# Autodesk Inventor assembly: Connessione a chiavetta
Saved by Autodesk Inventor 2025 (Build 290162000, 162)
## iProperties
Created: 2026-05
Part Number: Connessione a chiavetta
Document SubType Name: Assembly
Designer: Ryzen5700u
ClientObjectVersion: 1
Author: Ryzen5700u
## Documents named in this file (1)
- C:\Users\Ryzen5700u\Desktop\riduttore pompa\riduttore2\Design Accelerator\Connessione a chiavetta4.iam
